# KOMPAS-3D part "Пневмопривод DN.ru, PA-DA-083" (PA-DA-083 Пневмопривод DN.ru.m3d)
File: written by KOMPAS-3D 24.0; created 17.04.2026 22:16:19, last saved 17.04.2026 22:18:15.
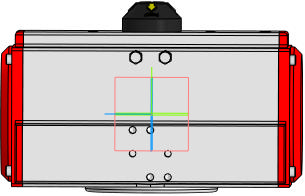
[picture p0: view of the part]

Document properties: Автор: DN.ru; Полное имя файла: C:\Работа\PA-DA-х Пневмопривод DN.ru\083\PA-DA-083 Пневмопривод DN.ru.m3d

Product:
- Part/product: Пневмопривод DN.ru  | designation PA-DA-083
    Масса: 3.1
    Раздел спецификации: Прочие изделия
    Примечание: D290-00295

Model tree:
1. Операция без истории:1

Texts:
  PA-DA-083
